(* Logix 5000 project; controller NXFE2_EDS_AOI_sample_RSLogix_V31 vendor 1 type 14 code 92 rev 31.11; software revision 31.00; part 3 of 4 *)
(* tags used below, declared in another part *)
   Status_Bits_MSW : INT;
   Status_Bits_LSW : INT;
   Blend_Move_Programmed : BOOL;
   Blend_Move_counter : COUNTER;
(* AMCI_NXFE2_Program_Blend_Move, continued *)

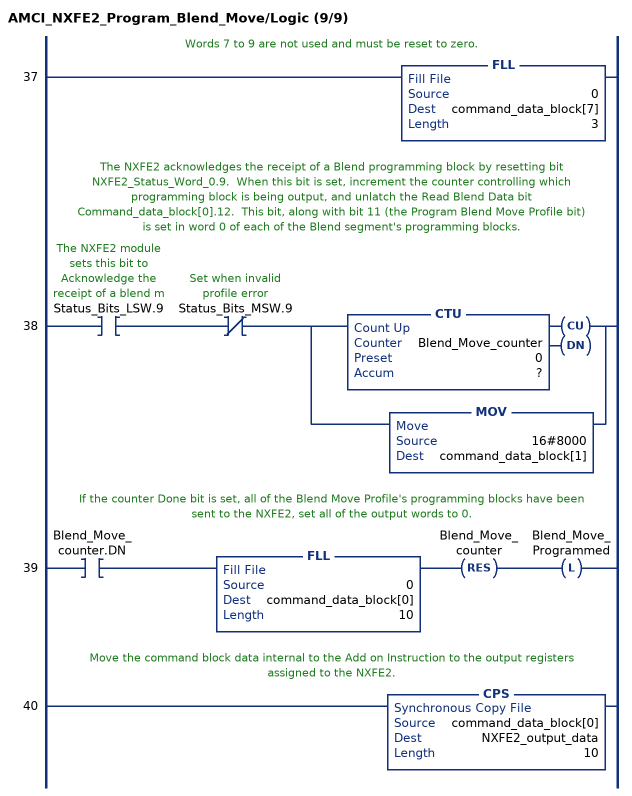
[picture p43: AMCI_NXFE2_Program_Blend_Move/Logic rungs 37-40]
   // Words 7 to 9 are not used and must be reset to zero.
   37: FLL(0,command_data_block[7],3);
   // The NXFE2 acknowledges the receipt of a Blend programming block by resetting bit NXFE2_Status_Word_0.9.  When this bit is set, increment the counter controlling which programming block is being output, and unlatch the Read Blend Data bit Command_data_block[0].12.  This bit, along with bit 11 (the Program Blend Move Profile bit)  is set in word 0 of each of the Blend segment's programming blocks.
   38: XIC(Status_Bits_LSW.9)XIO(Status_Bits_MSW.9)[CTU(Blend_Move_counter,?,?) ,MOV(16#8000,command_data_block[1]) ];
   // If the counter Done bit is set, all of the Blend Move Profile's programming blocks have been sent to the NXFE2, set all of the output words to 0.
   39: XIC(Blend_Move_counter.DN)FLL(0,command_data_block[0],10)RES(Blend_Move_counter)OTL(Blend_Move_Programmed);
   // Move the command block data internal to the Add on Instruction to the output registers assigned to the NXFE2.
   40: CPS(command_data_block[0],NXFE2_output_data,10);
END_ROUTINE
END_ADD_ON_INSTRUCTION

ADD_ON_INSTRUCTION AMCI_NXFE2_Registration_Move_CCW   (* revision 1.0, vendor AMCI, ExecuteEnableInFalse *)
VAR_INPUT
   Type_0_for_standard_1_for_indexed : BOOL;
   Axis_Status_bits : INT; {required}
   _0_normal_1_S_curve_acceleration : BOOL;
   _0_Triangular_1_Trapezoidal_S_Curve : BOOL;
   Stopping_Distance : DINT; {required}
   Programmed_Speed : DINT; {required}
   Acceleration : INT; {required}
   Deceleration : INT; {required}
END_VAR
VAR_OUTPUT
   EN : BOOL; {access Read Only, visible}
   Registration_Move_CCW_Occurring : BOOL; {access Read Only, visible}
   ER : BOOL; {access Read Only, visible}
END_VAR
VAR_IN_OUT
   NXFE2_output_data : _000A:NXFE2_0986AEB4:O:0; {required}
END_VAR
VAR
   command_data_block : INT[10];
        [1]   // Command Bits LSW
        [3]   // Lower Target Position
        [5]   // Lower Programmed Speed
        [0]   // Command Bits MSW
        [2]   // Upper Target Position
        [4]   // Upper Programmed Speed
END_VAR

ROUTINE EnableInFalse   (* ladder *)
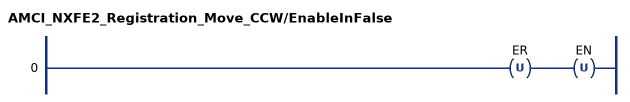
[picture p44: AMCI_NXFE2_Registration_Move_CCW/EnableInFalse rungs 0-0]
   0: OTU(ER)OTU(EN);
END_ROUTINE

ROUTINE Logic   (* ladder *)
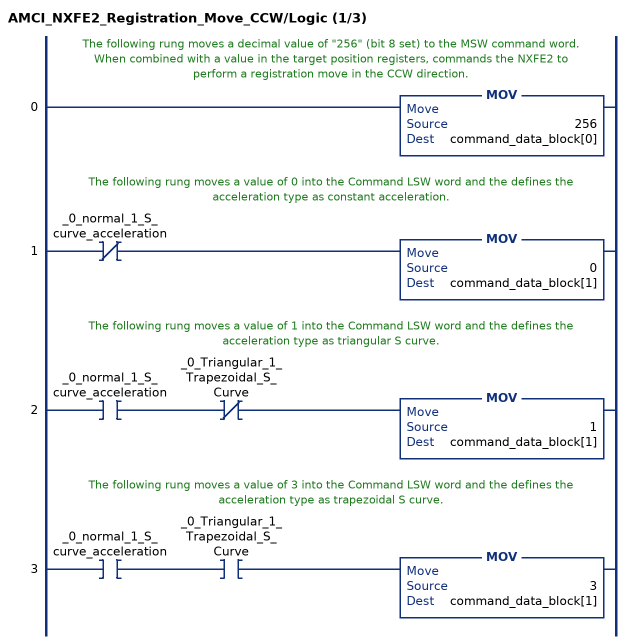
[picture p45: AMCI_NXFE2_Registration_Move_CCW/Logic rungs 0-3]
   // The following rung moves a decimal value of "256" (bit 8 set) to the MSW command word.  When combined with a value in the target position registers, commands the NXFE2 to perform a registration move in the CCW direction.
   0: MOV(256,command_data_block[0]);
   // The following rung moves a value of 0 into the Command LSW word and the defines the acceleration type as constant acceleration.
   1: XIO(_0_normal_1_S_curve_acceleration)MOV(0,command_data_block[1]);
   // The following rung moves a value of 1 into the Command LSW word and the defines the acceleration type as triangular S curve.
   2: XIC(_0_normal_1_S_curve_acceleration)XIO(_0_Triangular_1_Trapezoidal_S_Curve)MOV(1,command_data_block[1]);
   // The following rung moves a value of 3 into the Command LSW word and the defines the acceleration type as trapezoidal S curve.
   3: XIC(_0_normal_1_S_curve_acceleration)XIC(_0_Triangular_1_Trapezoidal_S_Curve)MOV(3,command_data_block[1]);
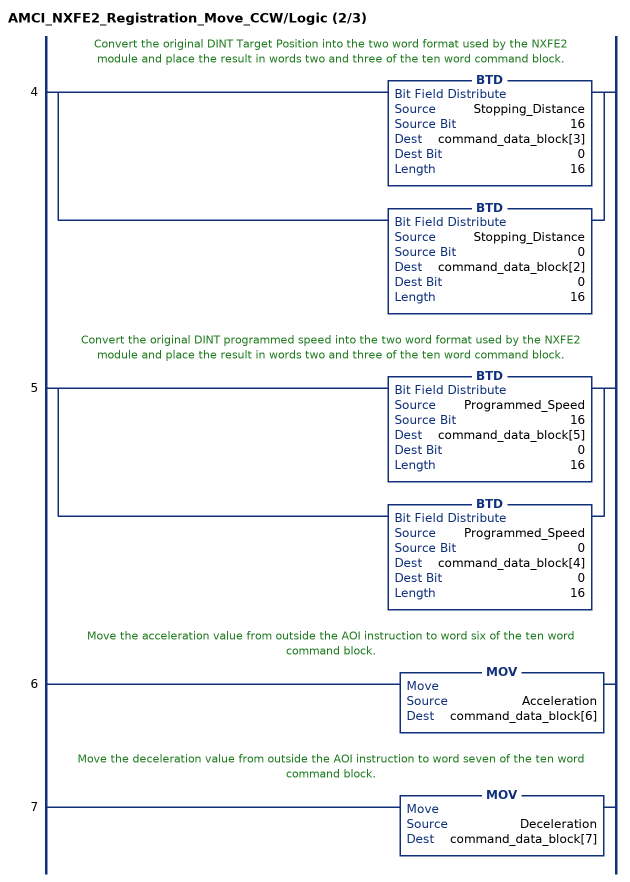
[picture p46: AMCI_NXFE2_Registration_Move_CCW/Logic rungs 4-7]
   // Convert the original DINT Target Position into the two word format used by the NXFE2 module and place the result in words two and three of the ten word command block.
   4: [BTD(Stopping_Distance,16,command_data_block[3],0,16) ,BTD(Stopping_Distance,0,command_data_block[2],0,16) ];
   // Convert the original DINT programmed speed into the two word format used by the NXFE2 module and place the result in words two and three of the ten word command block.
   5: [BTD(Programmed_Speed,16,command_data_block[5],0,16) ,BTD(Programmed_Speed,0,command_data_block[4],0,16) ];
   // Move the acceleration value from outside the AOI instruction to word six of the ten word command block.
   6: MOV(Acceleration,command_data_block[6]);
   // Move the deceleration value from outside the AOI instruction to word seven of the ten word command block.
   7: MOV(Deceleration,command_data_block[7]);
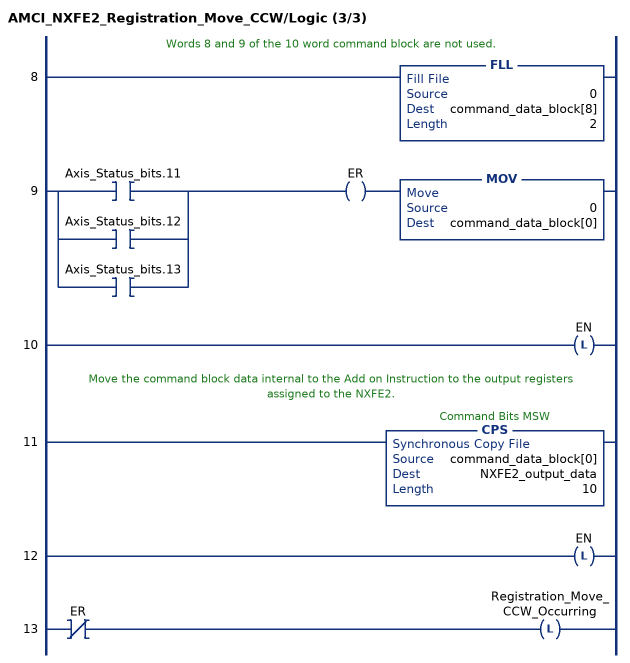
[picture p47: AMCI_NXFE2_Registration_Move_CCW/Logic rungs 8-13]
   // Words 8 and 9 of the 10 word command block are not used.
   8: FLL(0,command_data_block[8],2);
   9: [XIC(Axis_Status_bits.11) ,XIC(Axis_Status_bits.12) ,XIC(Axis_Status_bits.13) ]OTE(ER)MOV(0,command_data_block[0]);
   10: OTL(EN);
   // Move the command block data internal to the Add on Instruction to the output registers assigned to the NXFE2.
   11: CPS(command_data_block[0],NXFE2_output_data,10);
   12: OTL(EN);
   13: XIO(ER)OTL(Registration_Move_CCW_Occurring);
END_ROUTINE
END_ADD_ON_INSTRUCTION

ADD_ON_INSTRUCTION AMCI_NXFE2_Registration_Move_CW   (* revision 1.0, vendor AMCI, ExecuteEnableInFalse *)
VAR_INPUT
   Axis_Status_Bits : INT; {required}
   _0_normal_1_S_curve_acceleration : BOOL;
   _0_Triangular_1_Trapezoidal_S_Curve : BOOL;
   Stopping_Distance : DINT; {required}
   Programmed_Speed : DINT; {required}
   Acceleration : INT; {required}
   Deceleration : INT; {required}
END_VAR
VAR_IN_OUT
   NXFE2_output_data : _000A:NXFE2_0986AEB4:O:0; {required}
END_VAR
VAR_OUTPUT
   EN : BOOL; {access Read Only, visible}
   Registration_Move_CW_Occurring : BOOL; {access Read Only, visible}
   ER : BOOL; {access Read Only, visible}
END_VAR
VAR
   command_data_block : INT[10];
        [1]   // Command Bits LSW
        [3]   // Lower Target Position
        [5]   // Lower Programmed Speed
        [0]   // Command Bits MSW
        [2]   // Upper Target Position
        [4]   // Upper Programmed Speed
END_VAR

ROUTINE EnableInFalse   (* ladder *)
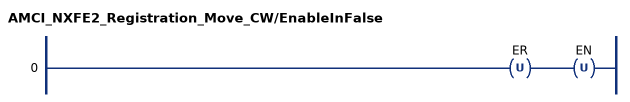
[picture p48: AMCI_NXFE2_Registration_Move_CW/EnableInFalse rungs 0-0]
   0: OTU(ER)OTU(EN);
END_ROUTINE

ROUTINE Logic   (* ladder *)
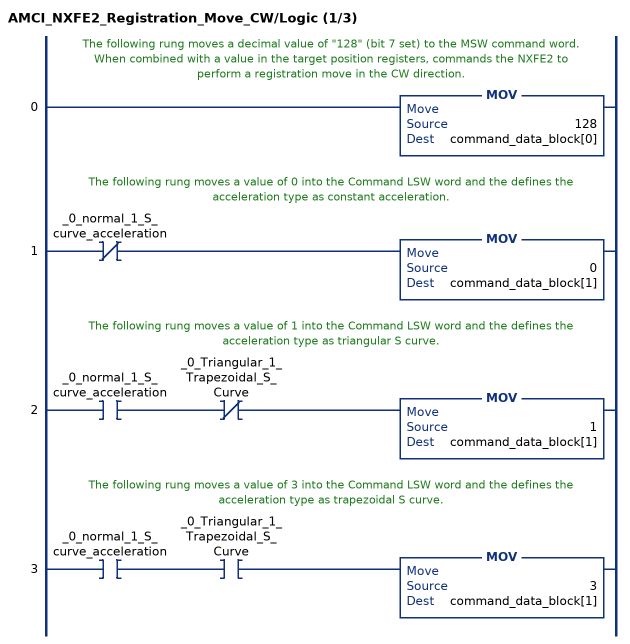
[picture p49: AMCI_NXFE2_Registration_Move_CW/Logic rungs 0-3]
   // The following rung moves a decimal value of "128" (bit 7 set) to the MSW command word.  When combined with a value in the target position registers, commands the NXFE2 to perform a registration move in the CW direction.
   0: MOV(128,command_data_block[0]);
   // The following rung moves a value of 0 into the Command LSW word and the defines the acceleration type as constant acceleration.
   1: XIO(_0_normal_1_S_curve_acceleration)MOV(0,command_data_block[1]);
   // The following rung moves a value of 1 into the Command LSW word and the defines the acceleration type as triangular S curve.
   2: XIC(_0_normal_1_S_curve_acceleration)XIO(_0_Triangular_1_Trapezoidal_S_Curve)MOV(1,command_data_block[1]);
   // The following rung moves a value of 3 into the Command LSW word and the defines the acceleration type as trapezoidal S curve.
   3: XIC(_0_normal_1_S_curve_acceleration)XIC(_0_Triangular_1_Trapezoidal_S_Curve)MOV(3,command_data_block[1]);
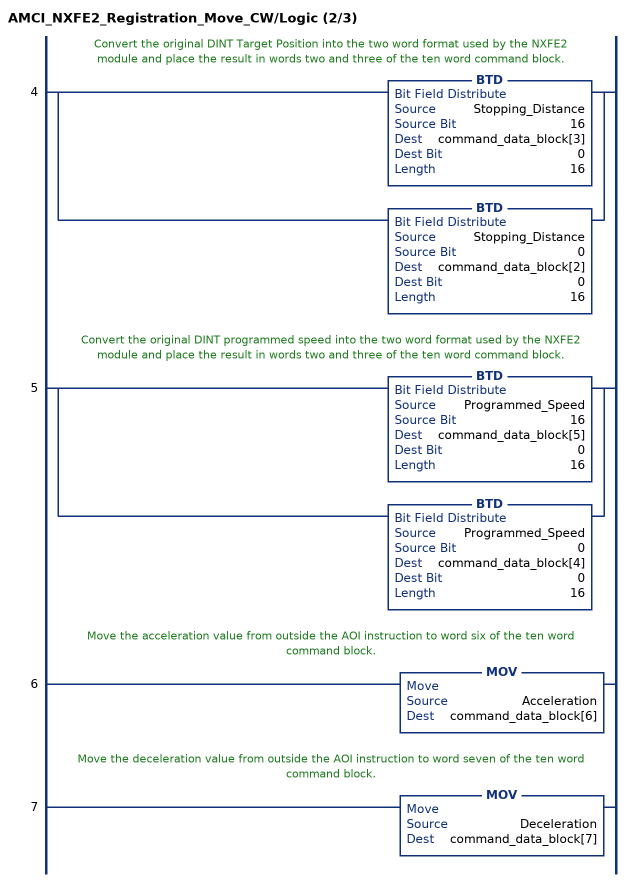
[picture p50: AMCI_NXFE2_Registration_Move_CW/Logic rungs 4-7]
   // Convert the original DINT Target Position into the two word format used by the NXFE2 module and place the result in words two and three of the ten word command block.
   4: [BTD(Stopping_Distance,16,command_data_block[3],0,16) ,BTD(Stopping_Distance,0,command_data_block[2],0,16) ];
   // Convert the original DINT programmed speed into the two word format used by the NXFE2 module and place the result in words two and three of the ten word command block.
   5: [BTD(Programmed_Speed,16,command_data_block[5],0,16) ,BTD(Programmed_Speed,0,command_data_block[4],0,16) ];
   // Move the acceleration value from outside the AOI instruction to word six of the ten word command block.
   6: MOV(Acceleration,command_data_block[6]);
   // Move the deceleration value from outside the AOI instruction to word seven of the ten word command block.
   7: MOV(Deceleration,command_data_block[7]);
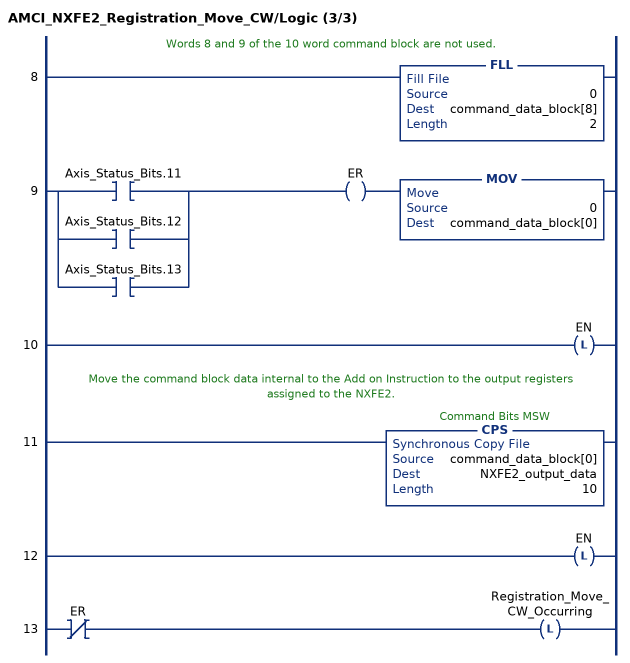
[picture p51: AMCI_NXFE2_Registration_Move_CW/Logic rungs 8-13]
   // Words 8 and 9 of the 10 word command block are not used.
   8: FLL(0,command_data_block[8],2);
   9: [XIC(Axis_Status_Bits.11) ,XIC(Axis_Status_Bits.12) ,XIC(Axis_Status_Bits.13) ]OTE(ER)MOV(0,command_data_block[0]);
   10: OTL(EN);
   // Move the command block data internal to the Add on Instruction to the output registers assigned to the NXFE2.
   11: CPS(command_data_block[0],NXFE2_output_data,10);
   12: OTL(EN);
   13: XIO(ER)OTL(Registration_Move_CW_Occurring);
END_ROUTINE
END_ADD_ON_INSTRUCTION

ADD_ON_INSTRUCTION AMCI_NXFE2_Relative_Move   (* revision 1.0, vendor AMCI, ExecuteEnableInFalse *)
VAR_INPUT
   Axis_Status_Bits : INT; {required}
   _0_normal_1_S_Curve_Acceleration : BOOL;
   _0_Triangular_1_Trapezoidal_S_Curve : BOOL;
   Target_Position : DINT; {required}
   Programmed_Speed : DINT; {required}
   Acceleration : INT; {required}
   Deceleration : INT; {required}
END_VAR
VAR_IN_OUT
   NXFE2_Output_Data : _000A:NXFE2_0986AEB4:O:0; {required}
END_VAR
VAR_OUTPUT
   EN : BOOL; {access Read Only, visible}
   ER : BOOL; {access Read Only, visible}
END_VAR
VAR
   command_data_block : INT[10];
        [1]   // Command Bits LSW
        [3]   // Lower Target Position
        [5]   // Lower Programmed Speed
        [0]   // Command Bits MSW
        [2]   // Upper Target Position
        [4]   // Upper Programmed Speed
END_VAR

ROUTINE EnableInFalse   (* ladder *)
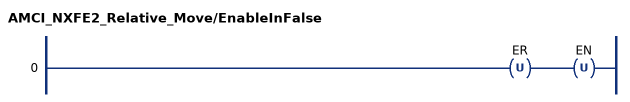
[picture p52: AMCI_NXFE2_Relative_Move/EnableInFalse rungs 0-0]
   0: OTU(ER)OTU(EN);
END_ROUTINE

ROUTINE Logic   (* ladder *)
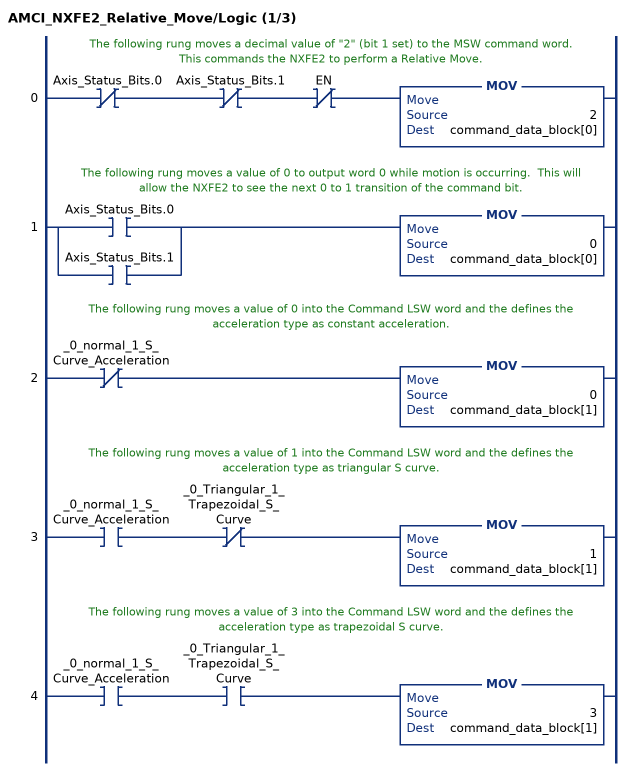
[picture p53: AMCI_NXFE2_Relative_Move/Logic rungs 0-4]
   // The following rung moves a decimal value of "2" (bit 1 set) to the MSW command word.  This commands the NXFE2 to perform a Relative Move.
   0: XIO(Axis_Status_Bits.0)XIO(Axis_Status_Bits.1)XIO(EN)MOV(2,command_data_block[0]);
   // The following rung moves a value of 0 to output word 0 while motion is occurring.  This will allow the NXFE2 to see the next 0 to 1 transition of the command bit.
   1: [XIC(Axis_Status_Bits.0) ,XIC(Axis_Status_Bits.1) ]MOV(0,command_data_block[0]);
   // The following rung moves a value of 0 into the Command LSW word and the defines the acceleration type as constant acceleration.
   2: XIO(_0_normal_1_S_Curve_Acceleration)MOV(0,command_data_block[1]);
   // The following rung moves a value of 1 into the Command LSW word and the defines the acceleration type as triangular S curve.
   3: XIC(_0_normal_1_S_Curve_Acceleration)XIO(_0_Triangular_1_Trapezoidal_S_Curve)MOV(1,command_data_block[1]);
   // The following rung moves a value of 3 into the Command LSW word and the defines the acceleration type as trapezoidal S curve.
   4: XIC(_0_normal_1_S_Curve_Acceleration)XIC(_0_Triangular_1_Trapezoidal_S_Curve)MOV(3,command_data_block[1]);
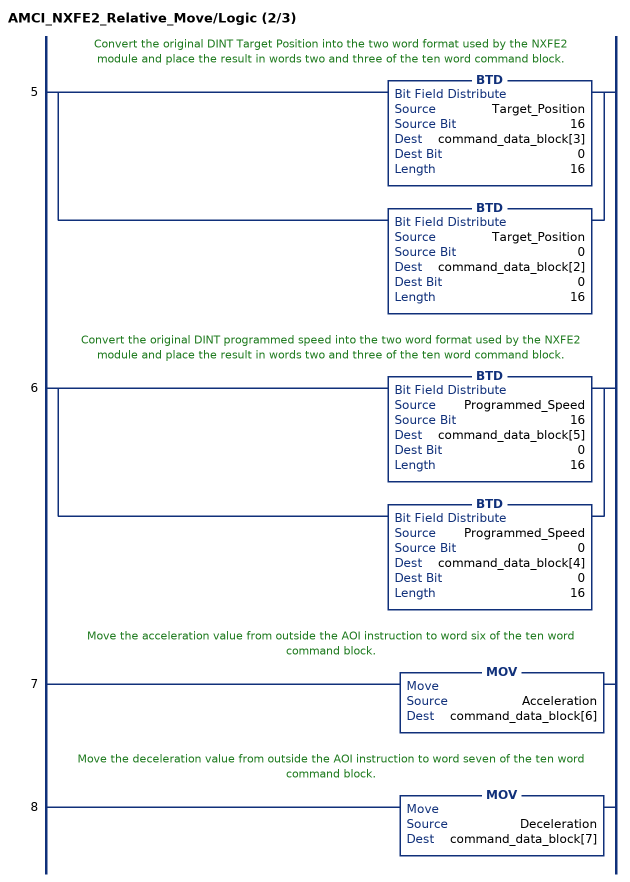
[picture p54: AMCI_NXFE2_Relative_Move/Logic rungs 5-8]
   // Convert the original DINT Target Position into the two word format used by the NXFE2 module and place the result in words two and three of the ten word command block.
   5: [BTD(Target_Position,16,command_data_block[3],0,16) ,BTD(Target_Position,0,command_data_block[2],0,16) ];
   // Convert the original DINT programmed speed into the two word format used by the NXFE2 module and place the result in words two and three of the ten word command block.
   6: [BTD(Programmed_Speed,16,command_data_block[5],0,16) ,BTD(Programmed_Speed,0,command_data_block[4],0,16) ];
   // Move the acceleration value from outside the AOI instruction to word six of the ten word command block.
   7: MOV(Acceleration,command_data_block[6]);
   // Move the deceleration value from outside the AOI instruction to word seven of the ten word command block.
   8: MOV(Deceleration,command_data_block[7]);
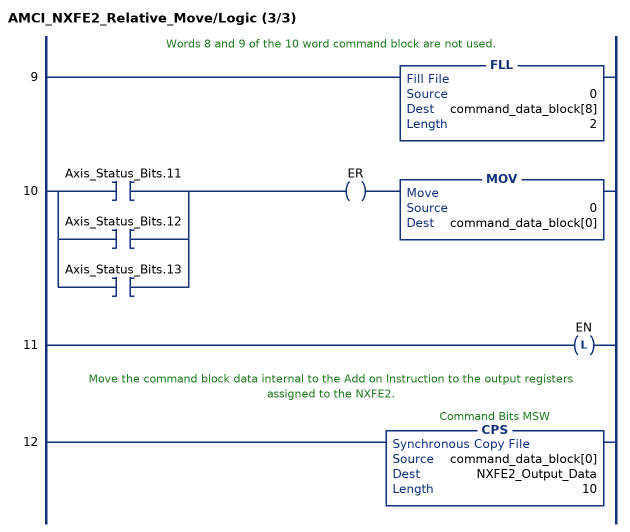
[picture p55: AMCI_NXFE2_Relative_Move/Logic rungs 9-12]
   // Words 8 and 9 of the 10 word command block are not used.
   9: FLL(0,command_data_block[8],2);
   10: [XIC(Axis_Status_Bits.11) ,XIC(Axis_Status_Bits.12) ,XIC(Axis_Status_Bits.13) ]OTE(ER)MOV(0,command_data_block[0]);
   11: OTL(EN);
   // Move the command block data internal to the Add on Instruction to the output registers assigned to the NXFE2.
   12: CPS(command_data_block[0],NXFE2_Output_Data,10);
END_ROUTINE
END_ADD_ON_INSTRUCTION

ADD_ON_INSTRUCTION AMCI_NXFE2_Reset_Errors   (* revision 1.1, vendor AMCI *)
// Revision note:
// Version 1.1 added the slot_axis number and the input parameters can now be tags or discrete values.
VAR_INPUT
   slot_number : INT; {required}
END_VAR
VAR_IN_OUT
   NXFE2_output_data : _000A:NXFE2_0986AEB4:O:0; {required}
END_VAR
VAR
   command_data_block : INT[10];
        [1]   // Command Bits LSW
        [3]   // Lower Target Position
        [5]   // Lower Programmed Speed
        [0]   // Command Bits MSW
        [2]   // Upper Target Position
        [4]   // Upper Programmed Speed
END_VAR

ROUTINE Logic   (* ladder *)
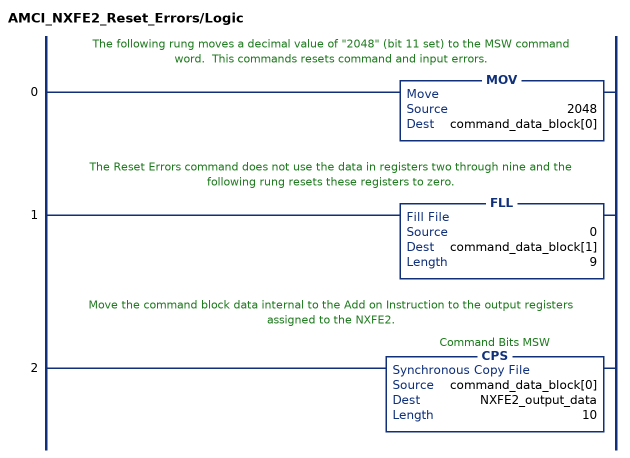
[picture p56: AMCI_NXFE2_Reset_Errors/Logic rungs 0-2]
   // The following rung moves a decimal value of "2048" (bit 11 set) to the MSW command word.  This commands resets command and input errors.
   0: MOV(2048,command_data_block[0]);
   // The Reset Errors command does not use the data in registers two through nine and the following rung resets these registers to zero.
   1: FLL(0,command_data_block[1],9);
   // Move the command block data internal to the Add on Instruction to the output registers assigned to the NXFE2.
   2: CPS(command_data_block[0],NXFE2_output_data,10);
END_ROUTINE
END_ADD_ON_INSTRUCTION

ADD_ON_INSTRUCTION AMCI_NXFE2_Resume   (* revision 1.0, vendor AMCI *)
VAR_IN_OUT
   NXFE2_output_data : _000A:NXFE2_0986AEB4:O:0; {required}
END_VAR
VAR
   command_data_block : INT[10];
        [1]   // Command Bits LSW
        [3]   // Lower Target Position
        [5]   // Lower Programmed Speed
        [0]   // Command Bits MSW
        [2]   // Upper Target Position
        [4]   // Upper Programmed Speed
END_VAR

ROUTINE Logic   (* ladder *)
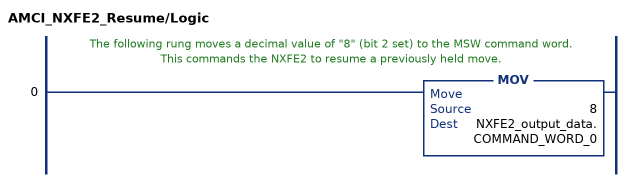
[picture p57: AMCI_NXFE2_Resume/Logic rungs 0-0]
   // The following rung moves a decimal value of "8" (bit 2 set) to the MSW command word.  This commands the NXFE2 to resume a previously held move.
   0: MOV(8,NXFE2_output_data.COMMAND_WORD_0);
END_ROUTINE
END_ADD_ON_INSTRUCTION

ADD_ON_INSTRUCTION AMCI_NXFE2_Run_Blend_Move   (* revision 1.0, vendor AMCI, ExecuteEnableInFalse *)
VAR_INPUT
   Axis_Status_bits : INT; {required}
   Direction_0_for_CW_1_for_CCW : BOOL; {required}
END_VAR
VAR_IN_OUT
   NXFE2_output_data : _000A:NXFE2_0986AEB4:O:0; {required}
END_VAR
VAR_OUTPUT
   EN : BOOL; {access Read Only, visible}
   ER : BOOL; {access Read Only, visible}
END_VAR
VAR
   command_data_block : INT[10];
        [1]   // Command Bits LSW
        [5]   // Lower Programmed Speed
        [0]   // Command Bits MSW
        [3]   // Lower Target Position
        [2]   // Upper Target Position
        [4]   // Upper Programmed Speed
END_VAR

ROUTINE EnableInFalse   (* ladder *)
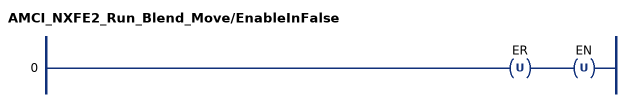
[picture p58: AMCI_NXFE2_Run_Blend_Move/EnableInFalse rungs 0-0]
   0: OTU(ER)OTU(EN);
END_ROUTINE

ROUTINE Logic   (* ladder *)
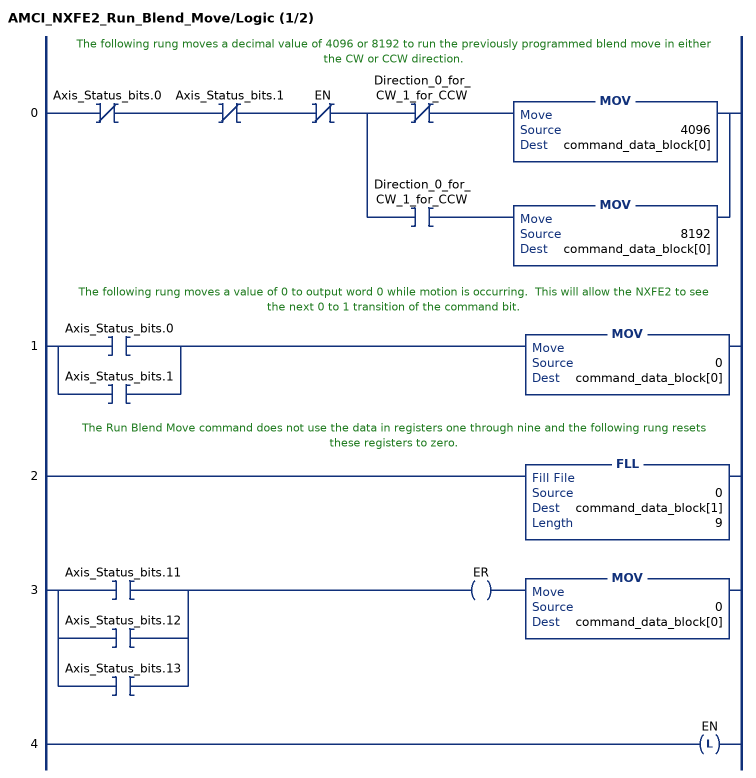
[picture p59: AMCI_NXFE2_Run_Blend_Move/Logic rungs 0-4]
   // The following rung moves a decimal value of 4096 or 8192 to run the previously programmed blend move in either the CW or CCW direction.
   0: XIO(Axis_Status_bits.0)XIO(Axis_Status_bits.1)XIO(EN)[XIO(Direction_0_for_CW_1_for_CCW) MOV(4096,command_data_block[0]) ,XIC(Direction_0_for_CW_1_for_CCW) MOV(8192,command_data_block[0]) ];
   // The following rung moves a value of 0 to output word 0 while motion is occurring.  This will allow the NXFE2 to see the next 0 to 1 transition of the command bit.
   1: [XIC(Axis_Status_bits.0) ,XIC(Axis_Status_bits.1) ]MOV(0,command_data_block[0]);
   // The Run Blend Move command does not use the data in registers one through nine and the following rung resets these registers to zero.
   2: FLL(0,command_data_block[1],9);
   3: [XIC(Axis_Status_bits.11) ,XIC(Axis_Status_bits.12) ,XIC(Axis_Status_bits.13) ]OTE(ER)MOV(0,command_data_block[0]);
   4: OTL(EN);
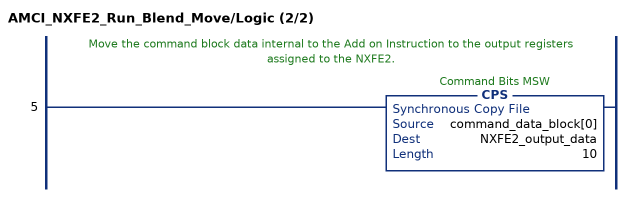
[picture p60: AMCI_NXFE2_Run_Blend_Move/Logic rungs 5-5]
   // Move the command block data internal to the Add on Instruction to the output registers assigned to the NXFE2.
   5: CPS(command_data_block[0],NXFE2_output_data,10);
END_ROUTINE
END_ADD_ON_INSTRUCTION
